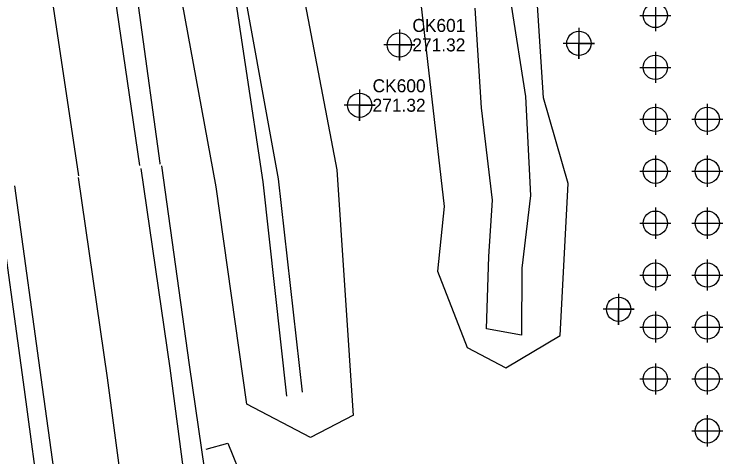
# Model space of a CAD drawing. Extents: x 1941547 to 1942851, y 663002 to 668358.
# Drawn here: x 1942636.4 to 1942773, y 663515 to 663600.2 of the extents above; entities that cross this region are included whole.
import ezdxf

# ---------------------------------------------------------------- set-up
doc = ezdxf.new("R2010")
doc.units = 0
for name, color, linetype in [('CTL GPS Vertical Cogo Elevation', 7, 'Continuous'), ('CTL NGS Vertical CELL', 7, 'Continuous'), ('Exist DTM Drainline Cogo Elevation', 7, 'Continuous'), ('Exist DTM QL2 LIDAR Elevation Point', 7, 'Continuous'), ('Exist Property Iron Pin Cogo Number', 7, 'Continuous'), ('Exist Roads EOP Cogo Point CELL', 7, 'Continuous'), ('Exist Roads EOT', 7, 'Continuous'), ('Exist Roads Soil', 7, 'Continuous'), ('Exist Utilities Telephone UG Cable SUE LOS C Cogo Elevation', 7, 'Continuous'), ('Exist Utilities Telephone UG FO SUE LOS C Cogo Elevation', 7, 'Continuous')]:
    doc.layers.add(name, color=color, linetype=linetype)

msp = doc.modelspace()

# ---------------------------------------------------------------- linework, layer by layer
at = {"layer": 'CTL NGS Vertical CELL'}
msp.add_line((1942688.97, 663526.69), (1942684.41, 663567.93), dxfattribs=at)
for points in [[(1942684.41, 663567.93), (1942677.62, 663613.22), (1942675.48, 663631.55), (1942668, 663679.97), (1942658.93, 663734.89), (1942658.92, 663746.56), (1942656.8, 663761.87)], [(1942691.99, 663527.43), (1942687.35, 663568.53), (1942679.24, 663613.49), (1942677.15, 663631.76), (1942671.36, 663680.68), (1942661.01, 663735.45), (1942659.52, 663746.66), (1942657.4, 663761.97)]]:
    msp.add_lwpolyline(points, dxfattribs=at)
at = {"layer": 'Exist DTM Drainline Cogo Elevation'}
for points in [[(1942710.66, 663597.32), (1942710.66, 663591.32), (1942710.66, 663594.32), (1942713.66, 663594.32), (1942707.66, 663594.32)], [(1942710.66, 663597.32), (1942710.66, 663591.32), (1942710.66, 663594.32), (1942713.66, 663594.32), (1942707.66, 663594.32)], [(1942745.26, 663597.62), (1942745.26, 663591.62), (1942745.26, 663594.62), (1942748.26, 663594.62), (1942742.26, 663594.62)], [(1942703, 663585.71), (1942703, 663579.71), (1942703, 663582.71), (1942706, 663582.71), (1942700, 663582.71)], [(1942703, 663585.71), (1942703, 663579.71), (1942703, 663582.71), (1942706, 663582.71), (1942700, 663582.71)], [(1942752.91, 663546.42), (1942752.91, 663540.42), (1942752.91, 663543.42), (1942755.91, 663543.42), (1942749.91, 663543.42)]]:
    msp.add_lwpolyline(points, dxfattribs=at)
for centre in [(1942710.66, 663594.32), (1942710.66, 663594.32), (1942745.26, 663594.62), (1942703, 663582.71), (1942703, 663582.71), (1942752.91, 663543.42)]:
    msp.add_circle(centre, 2.34, dxfattribs=at)
at = {"layer": 'Exist DTM QL2 LIDAR Elevation Point'}
for points in [[(1942760, 663603), (1942760, 663600)], [(1942757, 663600), (1942760, 663600)], [(1942760, 663600), (1942763, 663600)], [(1942760, 663600), (1942760, 663597)], [(1942760, 663593), (1942760, 663590)], [(1942757, 663590), (1942760, 663590)], [(1942760, 663590), (1942763, 663590)], [(1942760, 663590), (1942760, 663587)], [(1942760, 663583), (1942760, 663580)], [(1942770, 663583), (1942770, 663580)], [(1942757, 663580), (1942760, 663580)], [(1942760, 663580), (1942763, 663580)], [(1942760, 663580), (1942760, 663577)], [(1942767, 663580), (1942770, 663580)], [(1942770, 663580), (1942773, 663580)], [(1942770, 663580), (1942770, 663577)], [(1942760, 663573), (1942760, 663570)], [(1942770, 663573), (1942770, 663570)], [(1942757, 663570), (1942760, 663570)], [(1942760, 663570), (1942763, 663570)], [(1942760, 663570), (1942760, 663567)], [(1942767, 663570), (1942770, 663570)], [(1942770, 663570), (1942773, 663570)], [(1942770, 663570), (1942770, 663567)], [(1942760, 663563), (1942760, 663560)], [(1942770, 663563), (1942770, 663560)], [(1942757, 663560), (1942760, 663560)], [(1942760, 663560), (1942763, 663560)], [(1942760, 663560), (1942760, 663557)], [(1942767, 663560), (1942770, 663560)], [(1942770, 663560), (1942773, 663560)], [(1942770, 663560), (1942770, 663557)], [(1942760, 663553), (1942760, 663550)], [(1942770, 663553), (1942770, 663550)], [(1942757, 663550), (1942760, 663550)], [(1942760, 663550), (1942763, 663550)], [(1942760, 663550), (1942760, 663547)], [(1942767, 663550), (1942770, 663550)], [(1942770, 663550), (1942773, 663550)], [(1942770, 663550), (1942770, 663547)], [(1942760, 663543), (1942760, 663540)], [(1942770, 663543), (1942770, 663540)], [(1942757, 663540), (1942760, 663540)], [(1942760, 663540), (1942763, 663540)], [(1942760, 663540), (1942760, 663537)], [(1942767, 663540), (1942770, 663540)], [(1942770, 663540), (1942773, 663540)], [(1942770, 663540), (1942770, 663537)], [(1942760, 663533), (1942760, 663530)], [(1942770, 663533), (1942770, 663530)], [(1942757, 663530), (1942760, 663530)], [(1942760, 663530), (1942763, 663530)], [(1942760, 663530), (1942760, 663527)], [(1942767, 663530), (1942770, 663530)], [(1942770, 663530), (1942773, 663530)], [(1942770, 663530), (1942770, 663527)], [(1942770, 663523), (1942770, 663520)], [(1942767, 663520), (1942770, 663520)], [(1942770, 663520), (1942773, 663520)], [(1942770, 663520), (1942770, 663517)]]:
    msp.add_lwpolyline(points, dxfattribs=at)
for centre in [(1942760, 663600), (1942760, 663590), (1942760, 663580), (1942770, 663580), (1942760, 663570), (1942770, 663570), (1942760, 663560), (1942770, 663560), (1942760, 663550), (1942770, 663550), (1942760, 663540), (1942770, 663540), (1942760, 663530), (1942770, 663530), (1942770, 663520)]:
    msp.add_circle(centre, 2.34, dxfattribs=at)
at = {"layer": 'Exist Property Iron Pin Cogo Number'}
for points in [[(1942535.15, 664241.51), (1942545.15, 664190.98), (1942554.98, 664140.31), (1942564.32, 664090.5), (1942574.04, 664037.16), (1942583.23, 663987.29), (1942591.6, 663938.59), (1942600.26, 663885.84), (1942608.93, 663833.98), (1942616.95, 663781.65), (1942624.84, 663729.94), (1942632.77, 663678.03), (1942640.07, 663627.4), (1942648.8, 663569.13)], [(1942711.43, 663019.06), (1942706.58, 663070.67), (1942701.69, 663120.31), (1942696.68, 663171.66), (1942691.3, 663222.64), (1942685.77, 663274.43), (1942680.01, 663327.25), (1942674.04, 663378), (1942667.8, 663428.69), (1942660.91, 663481.57), (1942654.42, 663530.24), (1942648.8, 663568.81)]]:
    msp.add_lwpolyline(points, dxfattribs=at)
at = {"layer": 'Exist Roads EOT'}
for points in [[(1942546.97, 664243.63), (1942556.97, 664193.32), (1942566.94, 664142.09), (1942576.07, 664092.72), (1942586.16, 664038.02), (1942595.11, 663989.06), (1942603.48, 663940.87), (1942612.18, 663887.97), (1942620.88, 663835.09), (1942628.9, 663783.73), (1942636.85, 663731.29), (1942644.5, 663679.83), (1942652.2, 663628.27), (1942660.61, 663571.1)], [(1942723.44, 663020.52), (1942718.72, 663071.58), (1942713.79, 663121.81), (1942708.59, 663172.59), (1942703.27, 663224.11), (1942697.62, 663276.07), (1942691.88, 663328.67), (1942686.16, 663379.4), (1942679.84, 663430.59), (1942672.91, 663483.34), (1942666.48, 663532.09), (1942660.91, 663570.55)], [(1942699.01, 663017.78), (1942694.26, 663068.66), (1942689.28, 663118.96), (1942684.27, 663169.85), (1942678.85, 663220.92), (1942673.28, 663273.14), (1942667.46, 663325.8), (1942661.66, 663376.32), (1942655.59, 663427.02), (1942648.65, 663479.69), (1942641.9, 663528.43), (1942636.58, 663567.2)]]:
    msp.add_lwpolyline(points, dxfattribs=at)
at = {"layer": 'Exist Roads Soil'}
msp.add_lwpolyline([(1942673.41, 663516.48), (1942677.63, 663517.63), (1942680.6, 663510.19), (1942686.84, 663506.98), (1942702.84, 663508.72), (1942720.83, 663510.47), (1942739.37, 663509.43), (1942756.88, 663504.33), (1942771.12, 663496.19)], dxfattribs=at)
at = {"layer": 'Exist Utilities Telephone UG Cable SUE LOS C Cogo Elevation'}
for points in [[(1942551.4, 664244.16), (1942561.16, 664194.29), (1942571.17, 664142.93), (1942580.34, 664093.62), (1942590.26, 664039.1), (1942599.47, 663989.58), (1942608.09, 663941.73), (1942616.79, 663888.57), (1942625.47, 663835.77), (1942633.35, 663783.87), (1942641.57, 663732.16), (1942649.42, 663680.73), (1942656.69, 663628.65), (1942664.5, 663571.56), (1942664.5, 663571.37)], [(1942727.31, 663020.88), (1942723.13, 663072.03), (1942718.09, 663122.19), (1942712.96, 663173.03), (1942707.58, 663224.67), (1942701.96, 663276.6), (1942696.45, 663329.21), (1942690.84, 663380.05), (1942684.35, 663431.31), (1942677.27, 663484.06), (1942670.22, 663532.7), (1942664.87, 663571.07)], [(1942695.36, 663017.37), (1942690.59, 663068.32), (1942685.65, 663118.54), (1942680.1, 663169.38), (1942674.97, 663220.41), (1942669.56, 663272.64), (1942663.71, 663325.3), (1942658.09, 663375.53), (1942651.59, 663426.4), (1942644.95, 663479.19), (1942638.44, 663527.95), (1942633.01, 663566.84)]]:
    msp.add_lwpolyline(points, dxfattribs=at)
at = {"layer": 'Exist Utilities Telephone UG FO SUE LOS C Cogo Elevation'}
msp.add_line((1942701.85, 663522.98), (1942698.67, 663570.27), dxfattribs=at)
for points in [[(1942698.67, 663570.27), (1942690.05, 663615.32), (1942687.8, 663633.74), (1942681.77, 663680.9), (1942669.81, 663737.7), (1942669.16, 663768.43), (1942660.74, 663785.94), (1942654.22, 663840.51), (1942659.2, 663867.37), (1942662.57, 663894.02), (1942660.53, 663948.94), (1942653.89, 663997.65), (1942646.16, 664051.26), (1942643.52, 664103.09), (1942633.42, 664153.43), (1942621.98, 664209.98), (1942611.29, 664238.27), (1942628.17, 664250.61)], [(1942713.52, 663613.55), (1942719.3, 663563.18), (1942718.02, 663550.78), (1942723.76, 663536.03), (1942731.18, 663532.11), (1942741.65, 663538.34), (1942743.22, 663567.63), (1942738.46, 663584.14), (1942737.24, 663602.98)], [(1942701.8, 663523.04), (1942693.52, 663518.71), (1942681.29, 663525.16), (1942675.34, 663566.99), (1942667.2, 663611.44)], [(1942732.21, 663601.96), (1942735, 663584.37), (1942735.95, 663565.31), (1942734.24, 663551.32), (1942734.17, 663538.46), (1942727.43, 663539.63), (1942727.9, 663553.6), (1942728.64, 663564.46), (1942726.5, 663582.2), (1942725.3, 663601.43)]]:
    msp.add_lwpolyline(points, dxfattribs=at)

# ---------------------------------------------------------------- texts
at = {"layer": 'CTL GPS Vertical Cogo Elevation'}
for s, p in [('CK601', (1942713.16, 663596.83)), ('CK600', (1942705.5, 663585.21))]:
    msp.add_text(s, height=2.5, dxfattribs=at).set_placement(p)
at = {"layer": 'Exist Roads EOP Cogo Point CELL'}
for p in [(1942713.16, 663593.08), (1942705.5, 663581.46)]:
    msp.add_text('271.32', height=2.5, dxfattribs=at).set_placement(p)

doc.saveas('drawing.dxf')
